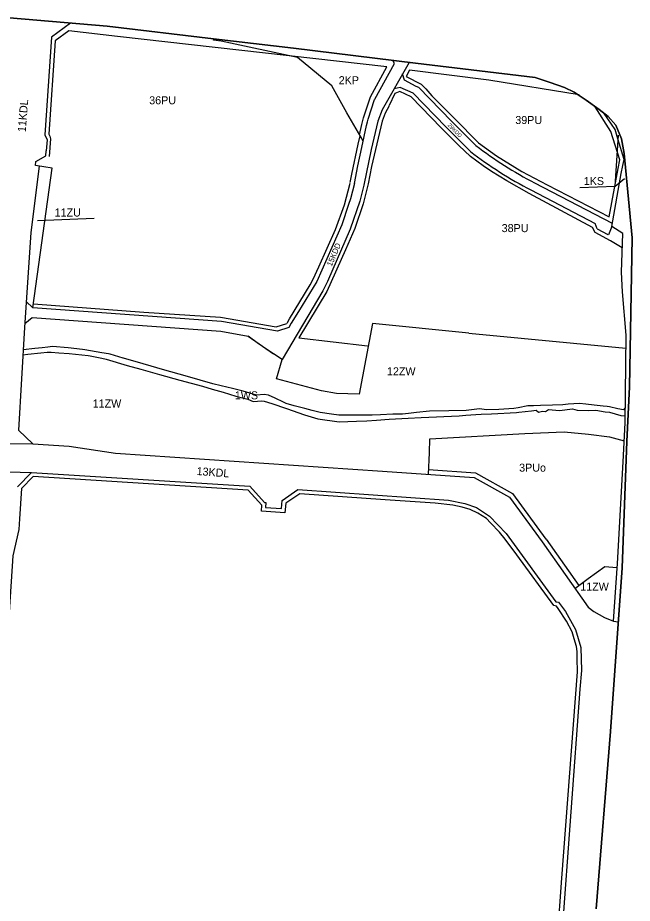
# Model space of a CAD drawing. Extents: x 7428203 to 7432868, y 5542672 to 5545406.
# Drawn here: x 7432101 to 7432868, y 5543958 to 5545064 of the extents above; entities that cross this region are included whole.
import ezdxf

# ---------------------------------------------------------------- set-up
doc = ezdxf.new("R2010")
doc.units = 0
for name, color, linetype in [('__LEGENDA_RAMKA_LOGO_PODZIAŁKA', 7, 'Continuous'), ('_GRANICA_MIASTA', 7, 'Continuous'), ('granicaBulwary', 7, 'Continuous'), ('MPZP_uchwalone_nieobowiazujace jeszcze_SZRAF', 7, 'Continuous')]:
    doc.layers.add(name, color=color, linetype=linetype)

msp = doc.modelspace()

# ---------------------------------------------------------------- linework, layer by layer
at = {"layer": '__LEGENDA_RAMKA_LOGO_PODZIAŁKA'}
msp.add_lwpolyline([(7432823.1, 5543950.8), (7432841.1, 5544172.5), (7432855.3, 5544376.5), (7432861.2, 5544534.5), (7432864.8, 5544602.7), (7432868.1, 5544788.7), (7432858, 5544894.1), (7432854.5, 5544912.5), (7432847.4, 5544929.6), (7432837.9, 5544940.2), (7432827, 5544949), (7432810.5, 5544960.6), (7432795.6, 5544970.6), (7432783.5, 5544976.3), (7432765.6, 5544982.6), (7432747, 5544989), (7432597.6, 5545006.8), (7432445.4, 5545025.5), (7432345.7, 5545037.2), (7432213.2, 5545053), (7432091.4, 5545063.6)], dxfattribs=at)
at = {"layer": '_GRANICA_MIASTA'}
for p, q in [((7432091.4, 5545063.6), (7432213.2, 5545053)), ((7432167.1, 5545057), (7432143.4, 5545039.5)), ((7432213.2, 5545053), (7432345.7, 5545037.2)), ((7432143.4, 5545039.5), (7432135.1, 5544917.3)), ((7432345.7, 5545037.2), (7432445.4, 5545025.5)), ((7432445.4, 5545025.5), (7432597.6, 5545006.8)), ((7432597.6, 5545006.8), (7432747, 5544989)), ((7432583.9, 5544985.6), (7432581.5, 5544993.4)), ((7432747, 5544989), (7432765.6, 5544982.6)), ((7432765.6, 5544982.6), (7432783.5, 5544976.3)), ((7432783.5, 5544976.3), (7432795.6, 5544970.6)), ((7432795.6, 5544970.6), (7432810.5, 5544960.6)), ((7432810.5, 5544960.6), (7432827, 5544949)), ((7432827, 5544949), (7432837.9, 5544940.2)), ((7432837.9, 5544940.2), (7432847.4, 5544929.6)), ((7432847.4, 5544929.6), (7432854.5, 5544912.5)), ((7432135.1, 5544917.3), (7432138, 5544911.1)), ((7432138, 5544911.1), (7432137.1, 5544897.6)), ((7432854.5, 5544912.5), (7432858, 5544894.1)), ((7432858, 5544894.1), (7432868.1, 5544788.7)), ((7432120.4, 5544701.3), (7432144.4, 5544875.6)), ((7432144.4, 5544875.6), (7432123.5, 5544879)), ((7432741.7, 5544848.5), (7432822, 5544806.7)), ((7432746.3, 5544857.3), (7432843.2, 5544807)), ((7432824.2, 5544800), (7432822, 5544806.7)), ((7432824.2, 5544800), (7432837.5, 5544793)), ((7432868.1, 5544788.7), (7432864.8, 5544602.7)), ((7432111.6, 5544701.9), (7432109.9, 5544676.8)), ((7432442.6, 5544682.2), (7432439.8, 5544676.9)), ((7432544.2, 5544681.6), (7432527.4, 5544593.6)), ((7432664.3, 5544669.7), (7432544.2, 5544681.6)), ((7432109.9, 5544676.8), (7432102.3, 5544548.6)), ((7432401.7, 5544656.6), (7432388.8, 5544666.1)), ((7432664.3, 5544669.7), (7432860.2, 5544650.8)), ((7432420.5, 5544644.1), (7432401.7, 5544656.6)), ((7432431.2, 5544636.9), (7432420.5, 5544644.1)), ((7432424.2, 5544612.6), (7432431.2, 5544636.9)), ((7432480.6, 5544597.7), (7432424.2, 5544612.6)), ((7432499, 5544594.4), (7432480.6, 5544597.7)), ((7432527.4, 5544593.6), (7432499, 5544594.4)), ((7432864.8, 5544602.7), (7432861.2, 5544534.5)), ((7432102.3, 5544548.6), (7432120.2, 5544531.7)), ((7432036.8, 5544532.5), (7432120.2, 5544531.7)), ((7432120.2, 5544531.7), (7432165.7, 5544528.6)), ((7432165.7, 5544528.6), (7432223.5, 5544519.9)), ((7432861.2, 5544534.5), (7432855.3, 5544376.5)), ((7432223.5, 5544519.9), (7432556.7, 5544497.3)), ((7432052.5, 5544497.8), (7432118.7, 5544495.9)), ((7432118.7, 5544495.9), (7432101.3, 5544477.8)), ((7432556.7, 5544497.3), (7432670.9, 5544489.6)), ((7432670.9, 5544489.6), (7432714.8, 5544465.1)), ((7432714.8, 5544465.1), (7432755.6, 5544409)), ((7432755.6, 5544409), (7432813, 5544327.6)), ((7432855.3, 5544376.5), (7432841.1, 5544172.5)), ((7432844.5, 5544310.2), (7432850.7, 5544309.3)), ((7432841.1, 5544172.5), (7432823.1, 5543950.8))]:
    msp.add_line(p, q, dxfattribs=at)
for points in [[(7432532.3, 5544909.7), (7432512.1, 5544944.8), (7432493.2, 5544978.5), (7432450.3, 5545014.1), (7432355.3, 5545034.5), (7432345.8, 5545035.4), (7432346.3, 5545037.1)], [(7432589.6, 5545007.8), (7432556.3, 5544948.6), (7432550.5, 5544934.4), (7432542.3, 5544899), (7432533.1, 5544854.4), (7432528.2, 5544834.5), (7432516.3, 5544799.5), (7432487.7, 5544734.4), (7432481.9, 5544722.7), (7432431.2, 5544636.9)], [(7432521.4, 5544856.8), (7432525.7, 5544878.8), (7432530.6, 5544901.5), (7432536.5, 5544928.9), (7432537.8, 5544933.5), (7432538.6, 5544936.9), (7432546.7, 5544961.7), (7432546.8, 5544962.1), (7432571.4, 5545006.6), (7432569.4, 5545010.2)], [(7432602, 5544976.3), (7432598.4, 5544977.9), (7432583.9, 5544985.6)], [(7432594.8, 5544969.4), (7432578.7, 5544976.6), (7432570.9, 5544974.7)], [(7432594.8, 5544969.4), (7432635.5, 5544927.4), (7432666.1, 5544896.7)], [(7432602, 5544976.3), (7432642.7, 5544934.4), (7432673, 5544904)], [(7432844.5, 5544310.2), (7432849.7, 5544382.2), (7432856.6, 5544508.9), (7432859.3, 5544557.8), (7432860.4, 5544667.1), (7432856.1, 5544721.2), (7432854.5, 5544746), (7432856.3, 5544794.2), (7432842.5, 5544802.9), (7432854.3, 5544869.1), (7432856.5, 5544879.2), (7432857.8, 5544886.5), (7432850.2, 5544912.5), (7432846.8, 5544924), (7432833, 5544944.2)], [(7432123.5, 5544879), (7432123.9, 5544884.2), (7432136.7, 5544891.3), (7432137.1, 5544897.6)], [(7432128.2, 5544878.2), (7432117.9, 5544795.6), (7432111.6, 5544701.9)], [(7432521.4, 5544856.8), (7432516.7, 5544837.6), (7432514.2, 5544830.3), (7432505.6, 5544804.8), (7432474.5, 5544734.3), (7432460.9, 5544711.6), (7432451.7, 5544696.9), (7432442.6, 5544682.2)], [(7432842.5, 5544802.9), (7432838.5, 5544792.5), (7432837.5, 5544793)], [(7432439.8, 5544676.9), (7432425.6, 5544672.2), (7432355.7, 5544684.1), (7432120.4, 5544701.3), (7432112.1, 5544709.1)], [(7432110.2, 5544682), (7432119.5, 5544689.3), (7432354.8, 5544672.1), (7432388.8, 5544666.1), (7432420.5, 5544644.1)], [(7432859.5, 5544575.4), (7432858.6, 5544575.5), (7432857.3, 5544574), (7432850.2, 5544575.1), (7432839.7, 5544577.6), (7432836.8, 5544578.2), (7432832, 5544578.7), (7432820.5, 5544579.9), (7432810, 5544580.9), (7432802.4, 5544582), (7432788.1, 5544580.9), (7432781.3, 5544580.4), (7432768.4, 5544579.9), (7432753.6, 5544579.4), (7432744.7, 5544579.1), (7432738, 5544578.9), (7432725.6, 5544576.6), (7432720.2, 5544575.5), (7432701.7, 5544574.5), (7432686.2, 5544573.8), (7432677.4, 5544575.3), (7432661.1, 5544573), (7432639.3, 5544572.7), (7432615, 5544572.2), (7432598.9, 5544570.7), (7432589, 5544569.4), (7432581.6, 5544568.5), (7432574.3, 5544568.6), (7432569.4, 5544568.5), (7432554.2, 5544567.8), (7432543.6, 5544567.4), (7432528.3, 5544567.4), (7432517.3, 5544567.4), (7432502.2, 5544567.2), (7432492.7, 5544568.7), (7432478.7, 5544570.8), (7432468.7, 5544573.3), (7432459.8, 5544575.5), (7432446.4, 5544579.1), (7432436.4, 5544581.9), (7432432.9, 5544583.7), (7432422.5, 5544588.5), (7432414.4, 5544592.3), (7432408.8, 5544593.2), (7432399.4, 5544592.5), (7432382.7, 5544597.1), (7432369.4, 5544600.6), (7432355.2, 5544603.9), (7432344.9, 5544606.3), (7432329.1, 5544611.1), (7432313.1, 5544615.7), (7432292.5, 5544621.6), (7432284.9, 5544623.7), (7432257.8, 5544631.4), (7432233.5, 5544638.4), (7432232.9, 5544638.7), (7432216.7, 5544643.5), (7432214.8, 5544643.9), (7432206.5, 5544645.3), (7432185.3, 5544649), (7432182.4, 5544649.5), (7432164.4, 5544651.6), (7432144.8, 5544652.9), (7432139.1, 5544652.4), (7432132, 5544651.5), (7432123, 5544650.6), (7432108.2, 5544649)], [(7432107.9, 5544642.8), (7432114, 5544643.4), (7432130.1, 5544645.1), (7432138.1, 5544645.9), (7432143.1, 5544645.9), (7432152.8, 5544645.3), (7432165.7, 5544644.5), (7432189.3, 5544641.8), (7432191.9, 5544641.4), (7432206.5, 5544638.3), (7432212, 5544637.1), (7432237.9, 5544629.5), (7432255.1, 5544624.7), (7432278.3, 5544618.2), (7432303.9, 5544611), (7432331.8, 5544603.4), (7432344.2, 5544600), (7432357.9, 5544595.9), (7432373.6, 5544590.9), (7432388.6, 5544587.1), (7432395, 5544584.5), (7432406, 5544585.1), (7432408.7, 5544584.9), (7432418.4, 5544581.9), (7432436.6, 5544575.6), (7432459.2, 5544567.7), (7432475.9, 5544562.9), (7432502.5, 5544559.2), (7432523.9, 5544559.7), (7432536.9, 5544560.1), (7432548.9, 5544561.2), (7432564.8, 5544562.3), (7432588.6, 5544563.5), (7432604.7, 5544564.6), (7432652.2, 5544566.5), (7432660.3, 5544567.2), (7432672.9, 5544568.3), (7432679.5, 5544568.6), (7432692.5, 5544568.8), (7432723.5, 5544570.6), (7432726.5, 5544570.9), (7432742.6, 5544572.9), (7432748.2, 5544573.5), (7432751.3, 5544571.1), (7432756.2, 5544572.2), (7432760, 5544571.8), (7432763.5, 5544574.5), (7432777.2, 5544573.2), (7432793.5, 5544575.4), (7432799.5, 5544573.4), (7432813.3, 5544573.3), (7432822.6, 5544573.6), (7432834.3, 5544571.5), (7432839.8, 5544571), (7432853.8, 5544566.9), (7432859.4, 5544566.3)], [(7432613.8, 5544493.5), (7432615.3, 5544520.1), (7432615.7, 5544537.9), (7432733.9, 5544544.5), (7432783.2, 5544546.5), (7432813.6, 5544543.8), (7432839.9, 5544540.4), (7432858.1, 5544535.3)], [(7432118.7, 5544495.9), (7432391.2, 5544478.5), (7432409.5, 5544458.4), (7432411.1, 5544458.2), (7432410.7, 5544452), (7432430.6, 5544450.7), (7432431.3, 5544460.6), (7432451.1, 5544474.4), (7432638.9, 5544461.3), (7432659.2, 5544457.1), (7432673.6, 5544451.9), (7432690.2, 5544441.4), (7432710.7, 5544419.7), (7432772.9, 5544334.2), (7432775.9, 5544333.9), (7432784.8, 5544322.3), (7432797.3, 5544299.7), (7432804.1, 5544277.1), (7432804.8, 5544248.6), (7432802.7, 5544225.3), (7432780.3, 5543918.7)], [(7432796.5, 5544351), (7432813, 5544363.3), (7432833.8, 5544378.3), (7432848.7, 5544377.2), (7432849.3, 5544377.1)], [(7432813, 5544327.6), (7432820.3, 5544322.2), (7432833.6, 5544314.5), (7432844.5, 5544310.2)]]:
    msp.add_lwpolyline(points, dxfattribs=at)
for centre, radius, start, end in [((7432975.3, 5545297.7), 496.3, 232.4836, 242.5254), ((7432975, 5545297.3), 505.8, 232.3612, 242.5337)]:
    msp.add_arc(centre, radius, start, end, dxfattribs=at)
at = {"layer": 'granicaBulwary'}
for p, q in [((7432846.9, 5544853.4), (7432850.9, 5544916.8)), ((7432197, 5544813), (7432126, 5544810.1))]:
    msp.add_line(p, q, dxfattribs=at)
msp.add_lwpolyline([(7432802.5, 5544851.6), (7432846.9, 5544853.4), (7432858.4, 5544862.7)], dxfattribs=at)
at = {"layer": 'MPZP_uchwalone_nieobowiazujace jeszcze_SZRAF'}
for p, q in [((7432530.7, 5544930.4), (7432532.8, 5544938.4)), ((7432527.9, 5544917.4), (7432530.7, 5544930.2)), ((7432530.7, 5544930.2), (7432530.7, 5544930.4)), ((7432452, 5544664), (7432537.8, 5544653.8)), ((7432614.1, 5544499.5), (7432672.6, 5544495.5)), ((7432672.6, 5544495.5), (7432718.9, 5544469.7)), ((7432718.9, 5544469.7), (7432760.4, 5544412.5)), ((7432760.5, 5544412.5), (7432801.3, 5544354.6))]:
    msp.add_line(p, q, dxfattribs=at)
for points in [[(7432165.4, 5545047.2), (7432148, 5545034.8), (7432140.2, 5544918.2), (7432141.4, 5544915.7), (7432142.4, 5544912.3), (7432140.5, 5544890.4)], [(7432562.1, 5545002.2), (7432226, 5545040.3), (7432165.4, 5545047.2)], [(7432541.6, 5544965), (7432562.1, 5545002.2)], [(7432590.4, 5544998.3), (7432585.9, 5544990.2)], [(7432802, 5544967.2), (7432689.2, 5544985.8), (7432590.1, 5544998.3)], [(7432585.9, 5544990.2), (7432604.9, 5544980.5), (7432610.4, 5544975), (7432618.1, 5544966.2), (7432646.2, 5544937.8), (7432676.2, 5544907.4), (7432698.9, 5544891.2), (7432730.3, 5544871.8), (7432762.1, 5544854.9), (7432839.1, 5544814.8)], [(7432855.6, 5544776.1), (7432841, 5544785.1), (7432821.9, 5544795.5), (7432818.3, 5544801.8), (7432739.4, 5544844), (7432711.7, 5544859.8), (7432692.5, 5544871.7), (7432682.3, 5544878.7), (7432666.1, 5544890.5), (7432651.6, 5544903.9), (7432629.7, 5544926.2), (7432592.3, 5544964.8), (7432578.2, 5544971.3), (7432572, 5544969.2), (7432564.9, 5544953.9)], [(7432532.9, 5544938.7), (7432541, 5544963.4), (7432541, 5544963.8)], [(7432564.9, 5544953.8), (7432559.9, 5544944.4), (7432555.9, 5544934.4), (7432542.9, 5544877.9), (7432538.5, 5544856.1), (7432532.4, 5544831.3), (7432522, 5544800.6), (7432510.5, 5544773.9), (7432487, 5544721.9), (7432452, 5544664)], [(7432839.1, 5544814.8), (7432850.5, 5544875.2), (7432852.7, 5544886.3), (7432841.5, 5544921.6), (7432821.9, 5544952.5)], [(7432516.3, 5544857.9), (7432516.6, 5544860), (7432518.4, 5544868.3), (7432526.3, 5544905.9), (7432528.5, 5544916.3)], [(7432497.7, 5544799.3), (7432509.3, 5544829.8), (7432516.1, 5544857.2)], [(7432437.7, 5544682.2), (7432440.5, 5544687.7), (7432466.4, 5544730.2), (7432470.2, 5544737.1), (7432477.2, 5544752.7), (7432497.7, 5544799.3), (7432497.7, 5544799.3)], [(7432121, 5544706.2), (7432258.8, 5544696.1), (7432354.5, 5544689.9), (7432424, 5544677.5), (7432437, 5544682)], [(7432388.8, 5544473.8), (7432120.7, 5544490.7), (7432106.1, 5544475.7), (7432103.7, 5544437.8), (7432102.9, 5544424.5), (7432095.5, 5544391.5), (7432087.5, 5544270.2), (7432075, 5544080), (7432070.5, 5544021), (7432069, 5544001.7), (7432073.6, 5543998.7), (7432071.8, 5543971)], [(7432775, 5543914.1), (7432780.4, 5543989), (7432799.6, 5544246.8), (7432799.5, 5544263.3), (7432799.2, 5544272.1), (7432798.5, 5544278.3), (7432795.6, 5544288), (7432793, 5544296.6), (7432785.9, 5544309.9), (7432775.8, 5544325.8), (7432773.4, 5544329), (7432770.1, 5544329.5), (7432724, 5544392.9), (7432709.7, 5544412.6), (7432702.5, 5544421.1), (7432691.4, 5544432.9), (7432686.2, 5544438.1), (7432675.5, 5544444.8), (7432665.7, 5544449.4), (7432656.1, 5544452.6), (7432644.4, 5544455), (7432622.4, 5544457.4), (7432559.9, 5544461.5), (7432453.5, 5544469.2), (7432436.1, 5544457.6), (7432434.7, 5544445.4), (7432405.4, 5544447.3), (7432405.8, 5544454.9), (7432388.9, 5544473.6)]]:
    msp.add_lwpolyline(points, dxfattribs=at)
for centre, radius, start, end in [((7432546.7, 5544962.2), 5.84, 150.9329, 164.0259), ((7432530.1, 5544939.3), 2.87, 340.9736, 347.6091)]:
    msp.add_arc(centre, radius, start, end, dxfattribs=at)

# ---------------------------------------------------------------- texts
at = {"layer": 'granicaBulwary'}
for s, p in [('2KP', (7432501.9, 5544980.6)), ('36PU', (7432265.5, 5544955.5)), ('39PU', (7432722.2, 5544930.9)), ('1KS', (7432807.6, 5544854.7)), ('11ZU', (7432147.5, 5544815.4)), ('38PU', (7432705.2, 5544795.9)), ('12ZW', (7432562.1, 5544617.1)), ('1WS', (7432372.3, 5544587.1)), ('11ZW', (7432195, 5544576.9)), ('3PUo', (7432727, 5544496.8)), ('11ZW', (7432803.2, 5544348.2))]:
    msp.add_text(s, height=10, dxfattribs=at).set_placement(p)
for s, height, rotation, p in [('11KDL', 10, 85.51, (7432111.4, 5544920.5)), ('29KDD', 4.9, 314.7935, (7432637.4, 5544929)), ('15KDD', 7, 67.2904, (7432493.2, 5544752.6)), ('13KDL', 10, 355.5331, (7432324.3, 5544492.7))]:
    msp.add_text(s, height=height, rotation=rotation, dxfattribs=at).set_placement(p)

doc.saveas('drawing.dxf')
